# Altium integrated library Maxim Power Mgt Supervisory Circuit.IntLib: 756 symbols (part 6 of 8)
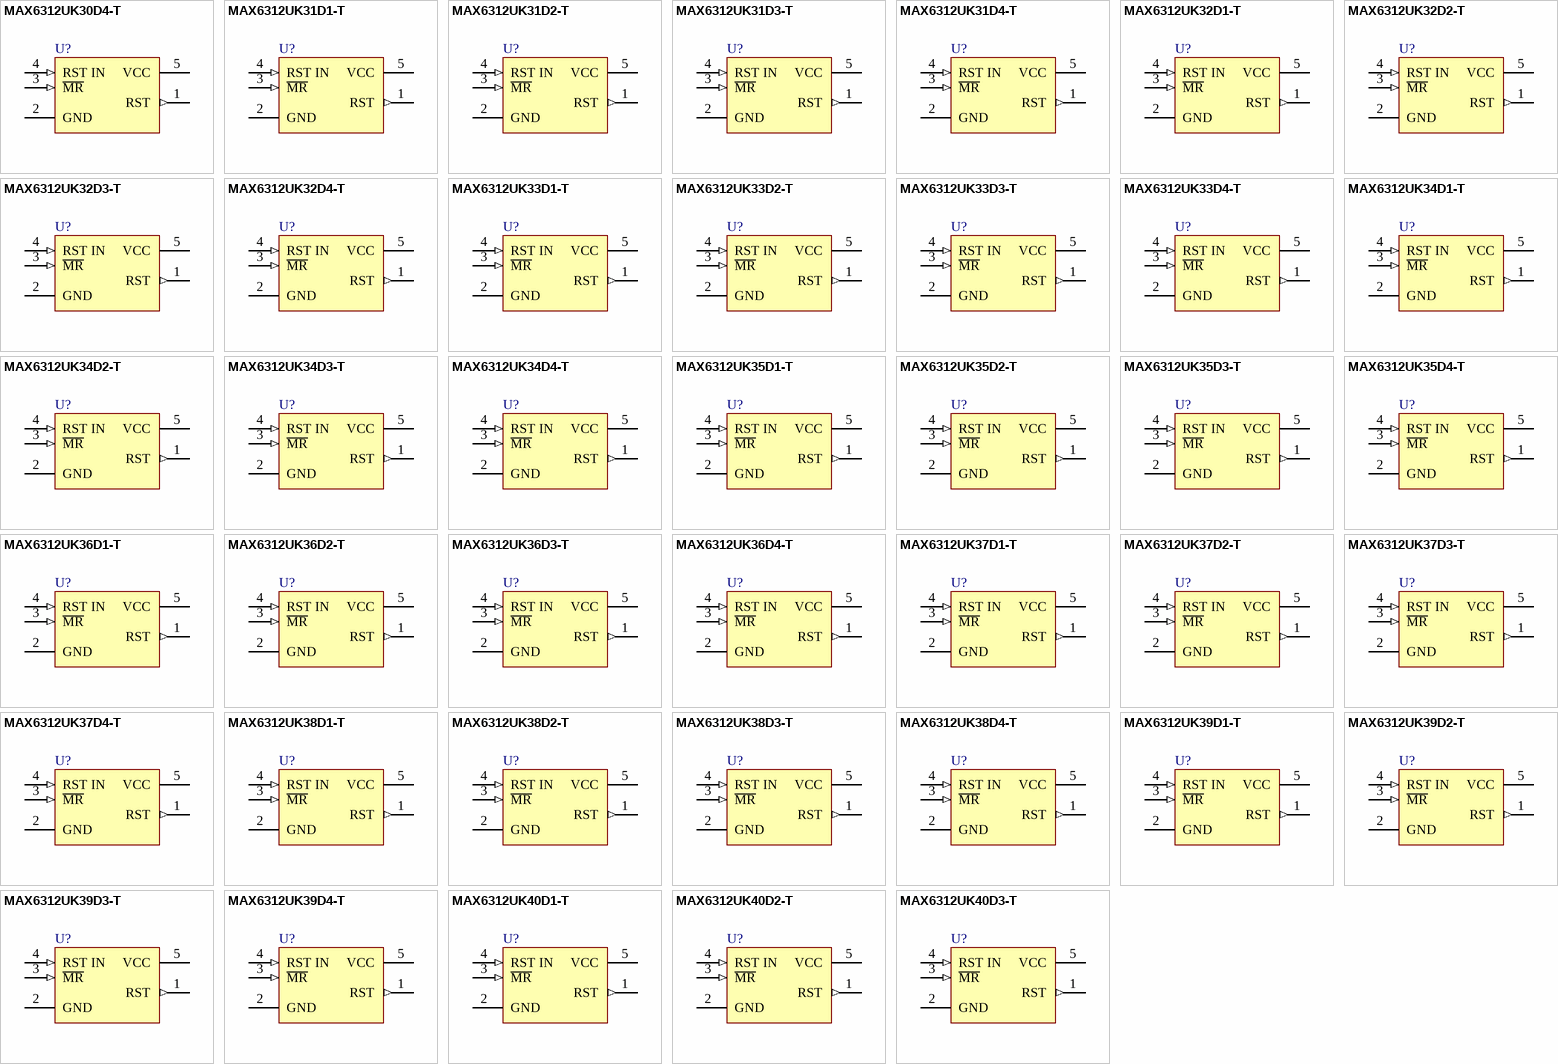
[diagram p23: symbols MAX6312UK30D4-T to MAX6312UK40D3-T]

## MAX6312UK35D3-T
designator U?
5-Pin, Multiple-Input, Programmable Reset IC
footprint SOT23-5_N (SOT23, 5-Leads, Body 2.9x1.6mm, Pitch 0.95mm, Lead Span 2.8mm, IPC Medium Density)
footprint SOT23-5_L (SOT23, 5-Leads, Body 2.9x1.6mm, Pitch 0.95mm, Lead Span 2.8mm, IPC High Density)
footprint SOT23-5_M (SOT23, 5-Leads, Body 2.9x1.6mm, Pitch 0.95mm, Lead Span 2.8mm, IPC Low Density)
pins: 1 RST (out), 2 GND (power), 3 ~{MR} (in), 4 RST IN (in), 5 VCC (power)

## MAX6312UK35D4-T
designator U?
5-Pin, Multiple-Input, Programmable Reset IC
footprint SOT23-5_N (SOT23, 5-Leads, Body 2.9x1.6mm, Pitch 0.95mm, Lead Span 2.8mm, IPC Medium Density)
footprint SOT23-5_L (SOT23, 5-Leads, Body 2.9x1.6mm, Pitch 0.95mm, Lead Span 2.8mm, IPC High Density)
footprint SOT23-5_M (SOT23, 5-Leads, Body 2.9x1.6mm, Pitch 0.95mm, Lead Span 2.8mm, IPC Low Density)
pins: 1 RST (out), 2 GND (power), 3 ~{MR} (in), 4 RST IN (in), 5 VCC (power)

## MAX6312UK36D1-T
designator U?
5-Pin, Multiple-Input, Programmable Reset IC
footprint SOT23-5_N (SOT23, 5-Leads, Body 2.9x1.6mm, Pitch 0.95mm, Lead Span 2.8mm, IPC Medium Density)
footprint SOT23-5_L (SOT23, 5-Leads, Body 2.9x1.6mm, Pitch 0.95mm, Lead Span 2.8mm, IPC High Density)
footprint SOT23-5_M (SOT23, 5-Leads, Body 2.9x1.6mm, Pitch 0.95mm, Lead Span 2.8mm, IPC Low Density)
pins: 1 RST (out), 2 GND (power), 3 ~{MR} (in), 4 RST IN (in), 5 VCC (power)

## MAX6312UK36D2-T
designator U?
5-Pin, Multiple-Input, Programmable Reset IC
footprint SOT23-5_N (SOT23, 5-Leads, Body 2.9x1.6mm, Pitch 0.95mm, Lead Span 2.8mm, IPC Medium Density)
footprint SOT23-5_L (SOT23, 5-Leads, Body 2.9x1.6mm, Pitch 0.95mm, Lead Span 2.8mm, IPC High Density)
footprint SOT23-5_M (SOT23, 5-Leads, Body 2.9x1.6mm, Pitch 0.95mm, Lead Span 2.8mm, IPC Low Density)
pins: 1 RST (out), 2 GND (power), 3 ~{MR} (in), 4 RST IN (in), 5 VCC (power)

## MAX6312UK36D3-T
designator U?
5-Pin, Multiple-Input, Programmable Reset IC
footprint SOT23-5_N (SOT23, 5-Leads, Body 2.9x1.6mm, Pitch 0.95mm, Lead Span 2.8mm, IPC Medium Density)
footprint SOT23-5_L (SOT23, 5-Leads, Body 2.9x1.6mm, Pitch 0.95mm, Lead Span 2.8mm, IPC High Density)
footprint SOT23-5_M (SOT23, 5-Leads, Body 2.9x1.6mm, Pitch 0.95mm, Lead Span 2.8mm, IPC Low Density)
pins: 1 RST (out), 2 GND (power), 3 ~{MR} (in), 4 RST IN (in), 5 VCC (power)

## MAX6312UK36D4-T
designator U?
5-Pin, Multiple-Input, Programmable Reset IC
footprint SOT23-5_N (SOT23, 5-Leads, Body 2.9x1.6mm, Pitch 0.95mm, Lead Span 2.8mm, IPC Medium Density)
footprint SOT23-5_L (SOT23, 5-Leads, Body 2.9x1.6mm, Pitch 0.95mm, Lead Span 2.8mm, IPC High Density)
footprint SOT23-5_M (SOT23, 5-Leads, Body 2.9x1.6mm, Pitch 0.95mm, Lead Span 2.8mm, IPC Low Density)
pins: 1 RST (out), 2 GND (power), 3 ~{MR} (in), 4 RST IN (in), 5 VCC (power)

## MAX6312UK37D1-T
designator U?
5-Pin, Multiple-Input, Programmable Reset IC
footprint SOT23-5_N (SOT23, 5-Leads, Body 2.9x1.6mm, Pitch 0.95mm, Lead Span 2.8mm, IPC Medium Density)
footprint SOT23-5_L (SOT23, 5-Leads, Body 2.9x1.6mm, Pitch 0.95mm, Lead Span 2.8mm, IPC High Density)
footprint SOT23-5_M (SOT23, 5-Leads, Body 2.9x1.6mm, Pitch 0.95mm, Lead Span 2.8mm, IPC Low Density)
pins: 1 RST (out), 2 GND (power), 3 ~{MR} (in), 4 RST IN (in), 5 VCC (power)

## MAX6312UK37D2-T
designator U?
5-Pin, Multiple-Input, Programmable Reset IC
footprint SOT23-5_N (SOT23, 5-Leads, Body 2.9x1.6mm, Pitch 0.95mm, Lead Span 2.8mm, IPC Medium Density)
footprint SOT23-5_L (SOT23, 5-Leads, Body 2.9x1.6mm, Pitch 0.95mm, Lead Span 2.8mm, IPC High Density)
footprint SOT23-5_M (SOT23, 5-Leads, Body 2.9x1.6mm, Pitch 0.95mm, Lead Span 2.8mm, IPC Low Density)
pins: 1 RST (out), 2 GND (power), 3 ~{MR} (in), 4 RST IN (in), 5 VCC (power)

## MAX6312UK37D3-T
designator U?
5-Pin, Multiple-Input, Programmable Reset IC
footprint SOT23-5_N (SOT23, 5-Leads, Body 2.9x1.6mm, Pitch 0.95mm, Lead Span 2.8mm, IPC Medium Density)
footprint SOT23-5_L (SOT23, 5-Leads, Body 2.9x1.6mm, Pitch 0.95mm, Lead Span 2.8mm, IPC High Density)
footprint SOT23-5_M (SOT23, 5-Leads, Body 2.9x1.6mm, Pitch 0.95mm, Lead Span 2.8mm, IPC Low Density)
pins: 1 RST (out), 2 GND (power), 3 ~{MR} (in), 4 RST IN (in), 5 VCC (power)

## MAX6312UK37D4-T
designator U?
5-Pin, Multiple-Input, Programmable Reset IC
footprint SOT23-5_N (SOT23, 5-Leads, Body 2.9x1.6mm, Pitch 0.95mm, Lead Span 2.8mm, IPC Medium Density)
footprint SOT23-5_L (SOT23, 5-Leads, Body 2.9x1.6mm, Pitch 0.95mm, Lead Span 2.8mm, IPC High Density)
footprint SOT23-5_M (SOT23, 5-Leads, Body 2.9x1.6mm, Pitch 0.95mm, Lead Span 2.8mm, IPC Low Density)
pins: 1 RST (out), 2 GND (power), 3 ~{MR} (in), 4 RST IN (in), 5 VCC (power)

## MAX6312UK38D1-T
designator U?
5-Pin, Multiple-Input, Programmable Reset IC
footprint SOT23-5_N (SOT23, 5-Leads, Body 2.9x1.6mm, Pitch 0.95mm, Lead Span 2.8mm, IPC Medium Density)
footprint SOT23-5_L (SOT23, 5-Leads, Body 2.9x1.6mm, Pitch 0.95mm, Lead Span 2.8mm, IPC High Density)
footprint SOT23-5_M (SOT23, 5-Leads, Body 2.9x1.6mm, Pitch 0.95mm, Lead Span 2.8mm, IPC Low Density)
pins: 1 RST (out), 2 GND (power), 3 ~{MR} (in), 4 RST IN (in), 5 VCC (power)

## MAX6312UK38D2-T
designator U?
5-Pin, Multiple-Input, Programmable Reset IC
footprint SOT23-5_N (SOT23, 5-Leads, Body 2.9x1.6mm, Pitch 0.95mm, Lead Span 2.8mm, IPC Medium Density)
footprint SOT23-5_L (SOT23, 5-Leads, Body 2.9x1.6mm, Pitch 0.95mm, Lead Span 2.8mm, IPC High Density)
footprint SOT23-5_M (SOT23, 5-Leads, Body 2.9x1.6mm, Pitch 0.95mm, Lead Span 2.8mm, IPC Low Density)
pins: 1 RST (out), 2 GND (power), 3 ~{MR} (in), 4 RST IN (in), 5 VCC (power)

## MAX6312UK38D3-T
designator U?
5-Pin, Multiple-Input, Programmable Reset IC
footprint SOT23-5_N (SOT23, 5-Leads, Body 2.9x1.6mm, Pitch 0.95mm, Lead Span 2.8mm, IPC Medium Density)
footprint SOT23-5_L (SOT23, 5-Leads, Body 2.9x1.6mm, Pitch 0.95mm, Lead Span 2.8mm, IPC High Density)
footprint SOT23-5_M (SOT23, 5-Leads, Body 2.9x1.6mm, Pitch 0.95mm, Lead Span 2.8mm, IPC Low Density)
pins: 1 RST (out), 2 GND (power), 3 ~{MR} (in), 4 RST IN (in), 5 VCC (power)

## MAX6312UK38D4-T
designator U?
5-Pin, Multiple-Input, Programmable Reset IC
footprint SOT23-5_N (SOT23, 5-Leads, Body 2.9x1.6mm, Pitch 0.95mm, Lead Span 2.8mm, IPC Medium Density)
footprint SOT23-5_L (SOT23, 5-Leads, Body 2.9x1.6mm, Pitch 0.95mm, Lead Span 2.8mm, IPC High Density)
footprint SOT23-5_M (SOT23, 5-Leads, Body 2.9x1.6mm, Pitch 0.95mm, Lead Span 2.8mm, IPC Low Density)
pins: 1 RST (out), 2 GND (power), 3 ~{MR} (in), 4 RST IN (in), 5 VCC (power)

## MAX6312UK39D1-T
designator U?
5-Pin, Multiple-Input, Programmable Reset IC
footprint SOT23-5_N (SOT23, 5-Leads, Body 2.9x1.6mm, Pitch 0.95mm, Lead Span 2.8mm, IPC Medium Density)
footprint SOT23-5_L (SOT23, 5-Leads, Body 2.9x1.6mm, Pitch 0.95mm, Lead Span 2.8mm, IPC High Density)
footprint SOT23-5_M (SOT23, 5-Leads, Body 2.9x1.6mm, Pitch 0.95mm, Lead Span 2.8mm, IPC Low Density)
pins: 1 RST (out), 2 GND (power), 3 ~{MR} (in), 4 RST IN (in), 5 VCC (power)

## MAX6312UK39D2-T
designator U?
5-Pin, Multiple-Input, Programmable Reset IC
footprint SOT23-5_N (SOT23, 5-Leads, Body 2.9x1.6mm, Pitch 0.95mm, Lead Span 2.8mm, IPC Medium Density)
footprint SOT23-5_L (SOT23, 5-Leads, Body 2.9x1.6mm, Pitch 0.95mm, Lead Span 2.8mm, IPC High Density)
footprint SOT23-5_M (SOT23, 5-Leads, Body 2.9x1.6mm, Pitch 0.95mm, Lead Span 2.8mm, IPC Low Density)
pins: 1 RST (out), 2 GND (power), 3 ~{MR} (in), 4 RST IN (in), 5 VCC (power)

## MAX6312UK39D3-T
designator U?
5-Pin, Multiple-Input, Programmable Reset IC
footprint SOT23-5_N (SOT23, 5-Leads, Body 2.9x1.6mm, Pitch 0.95mm, Lead Span 2.8mm, IPC Medium Density)
footprint SOT23-5_L (SOT23, 5-Leads, Body 2.9x1.6mm, Pitch 0.95mm, Lead Span 2.8mm, IPC High Density)
footprint SOT23-5_M (SOT23, 5-Leads, Body 2.9x1.6mm, Pitch 0.95mm, Lead Span 2.8mm, IPC Low Density)
pins: 1 RST (out), 2 GND (power), 3 ~{MR} (in), 4 RST IN (in), 5 VCC (power)

## MAX6312UK39D4-T
designator U?
5-Pin, Multiple-Input, Programmable Reset IC
footprint SOT23-5_N (SOT23, 5-Leads, Body 2.9x1.6mm, Pitch 0.95mm, Lead Span 2.8mm, IPC Medium Density)
footprint SOT23-5_L (SOT23, 5-Leads, Body 2.9x1.6mm, Pitch 0.95mm, Lead Span 2.8mm, IPC High Density)
footprint SOT23-5_M (SOT23, 5-Leads, Body 2.9x1.6mm, Pitch 0.95mm, Lead Span 2.8mm, IPC Low Density)
pins: 1 RST (out), 2 GND (power), 3 ~{MR} (in), 4 RST IN (in), 5 VCC (power)

## MAX6312UK40D1-T
designator U?
5-Pin, Multiple-Input, Programmable Reset IC
footprint SOT23-5_N (SOT23, 5-Leads, Body 2.9x1.6mm, Pitch 0.95mm, Lead Span 2.8mm, IPC Medium Density)
footprint SOT23-5_L (SOT23, 5-Leads, Body 2.9x1.6mm, Pitch 0.95mm, Lead Span 2.8mm, IPC High Density)
footprint SOT23-5_M (SOT23, 5-Leads, Body 2.9x1.6mm, Pitch 0.95mm, Lead Span 2.8mm, IPC Low Density)
pins: 1 RST (out), 2 GND (power), 3 ~{MR} (in), 4 RST IN (in), 5 VCC (power)

## MAX6312UK40D2-T
designator U?
5-Pin, Multiple-Input, Programmable Reset IC
footprint SOT23-5_N (SOT23, 5-Leads, Body 2.9x1.6mm, Pitch 0.95mm, Lead Span 2.8mm, IPC Medium Density)
footprint SOT23-5_L (SOT23, 5-Leads, Body 2.9x1.6mm, Pitch 0.95mm, Lead Span 2.8mm, IPC High Density)
footprint SOT23-5_M (SOT23, 5-Leads, Body 2.9x1.6mm, Pitch 0.95mm, Lead Span 2.8mm, IPC Low Density)
pins: 1 RST (out), 2 GND (power), 3 ~{MR} (in), 4 RST IN (in), 5 VCC (power)

## MAX6312UK40D3-T
designator U?
5-Pin, Multiple-Input, Programmable Reset IC
footprint SOT23-5_N (SOT23, 5-Leads, Body 2.9x1.6mm, Pitch 0.95mm, Lead Span 2.8mm, IPC Medium Density)
footprint SOT23-5_L (SOT23, 5-Leads, Body 2.9x1.6mm, Pitch 0.95mm, Lead Span 2.8mm, IPC High Density)
footprint SOT23-5_M (SOT23, 5-Leads, Body 2.9x1.6mm, Pitch 0.95mm, Lead Span 2.8mm, IPC Low Density)
pins: 1 RST (out), 2 GND (power), 3 ~{MR} (in), 4 RST IN (in), 5 VCC (power)

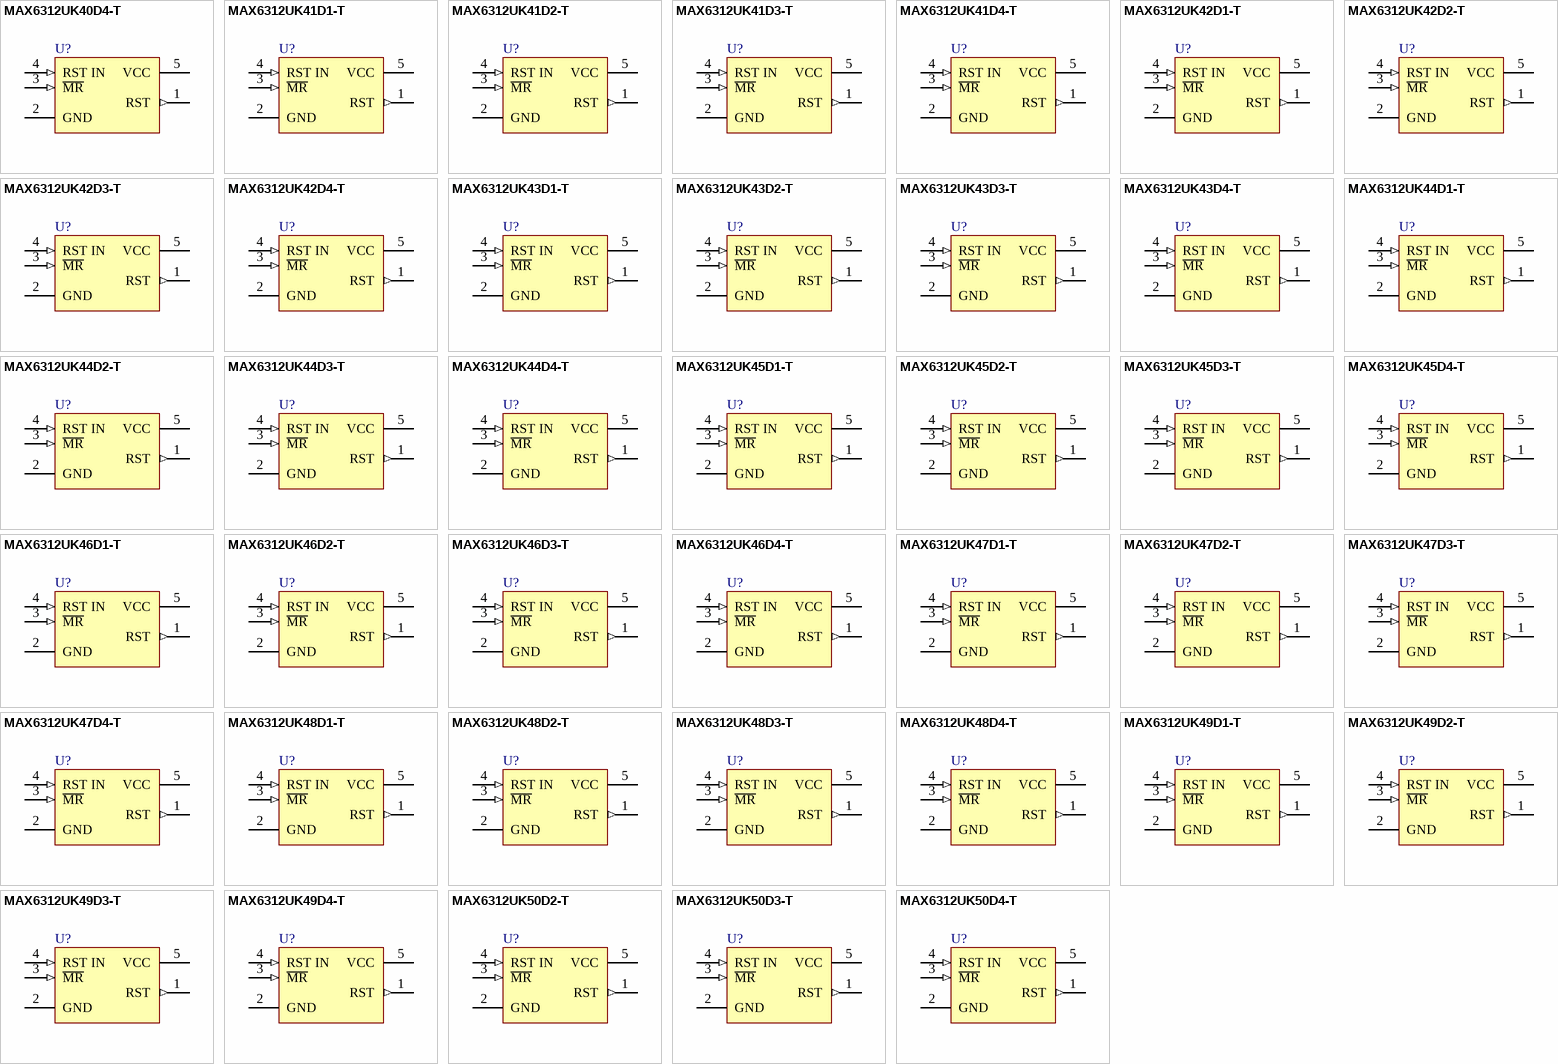
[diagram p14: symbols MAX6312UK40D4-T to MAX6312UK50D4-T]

## MAX6312UK40D4-T
designator U?
5-Pin, Multiple-Input, Programmable Reset IC
footprint SOT23-5_N (SOT23, 5-Leads, Body 2.9x1.6mm, Pitch 0.95mm, Lead Span 2.8mm, IPC Medium Density)
footprint SOT23-5_L (SOT23, 5-Leads, Body 2.9x1.6mm, Pitch 0.95mm, Lead Span 2.8mm, IPC High Density)
footprint SOT23-5_M (SOT23, 5-Leads, Body 2.9x1.6mm, Pitch 0.95mm, Lead Span 2.8mm, IPC Low Density)
pins: 1 RST (out), 2 GND (power), 3 ~{MR} (in), 4 RST IN (in), 5 VCC (power)

## MAX6312UK41D1-T
designator U?
5-Pin, Multiple-Input, Programmable Reset IC
footprint SOT23-5_N (SOT23, 5-Leads, Body 2.9x1.6mm, Pitch 0.95mm, Lead Span 2.8mm, IPC Medium Density)
footprint SOT23-5_L (SOT23, 5-Leads, Body 2.9x1.6mm, Pitch 0.95mm, Lead Span 2.8mm, IPC High Density)
footprint SOT23-5_M (SOT23, 5-Leads, Body 2.9x1.6mm, Pitch 0.95mm, Lead Span 2.8mm, IPC Low Density)
pins: 1 RST (out), 2 GND (power), 3 ~{MR} (in), 4 RST IN (in), 5 VCC (power)

## MAX6312UK41D2-T
designator U?
5-Pin, Multiple-Input, Programmable Reset IC
footprint SOT23-5_N (SOT23, 5-Leads, Body 2.9x1.6mm, Pitch 0.95mm, Lead Span 2.8mm, IPC Medium Density)
footprint SOT23-5_L (SOT23, 5-Leads, Body 2.9x1.6mm, Pitch 0.95mm, Lead Span 2.8mm, IPC High Density)
footprint SOT23-5_M (SOT23, 5-Leads, Body 2.9x1.6mm, Pitch 0.95mm, Lead Span 2.8mm, IPC Low Density)
pins: 1 RST (out), 2 GND (power), 3 ~{MR} (in), 4 RST IN (in), 5 VCC (power)

## MAX6312UK41D3-T
designator U?
5-Pin, Multiple-Input, Programmable Reset IC
footprint SOT23-5_N (SOT23, 5-Leads, Body 2.9x1.6mm, Pitch 0.95mm, Lead Span 2.8mm, IPC Medium Density)
footprint SOT23-5_L (SOT23, 5-Leads, Body 2.9x1.6mm, Pitch 0.95mm, Lead Span 2.8mm, IPC High Density)
footprint SOT23-5_M (SOT23, 5-Leads, Body 2.9x1.6mm, Pitch 0.95mm, Lead Span 2.8mm, IPC Low Density)
pins: 1 RST (out), 2 GND (power), 3 ~{MR} (in), 4 RST IN (in), 5 VCC (power)

## MAX6312UK41D4-T
designator U?
5-Pin, Multiple-Input, Programmable Reset IC
footprint SOT23-5_N (SOT23, 5-Leads, Body 2.9x1.6mm, Pitch 0.95mm, Lead Span 2.8mm, IPC Medium Density)
footprint SOT23-5_L (SOT23, 5-Leads, Body 2.9x1.6mm, Pitch 0.95mm, Lead Span 2.8mm, IPC High Density)
footprint SOT23-5_M (SOT23, 5-Leads, Body 2.9x1.6mm, Pitch 0.95mm, Lead Span 2.8mm, IPC Low Density)
pins: 1 RST (out), 2 GND (power), 3 ~{MR} (in), 4 RST IN (in), 5 VCC (power)

## MAX6312UK42D1-T
designator U?
5-Pin, Multiple-Input, Programmable Reset IC
footprint SOT23-5_N (SOT23, 5-Leads, Body 2.9x1.6mm, Pitch 0.95mm, Lead Span 2.8mm, IPC Medium Density)
footprint SOT23-5_L (SOT23, 5-Leads, Body 2.9x1.6mm, Pitch 0.95mm, Lead Span 2.8mm, IPC High Density)
footprint SOT23-5_M (SOT23, 5-Leads, Body 2.9x1.6mm, Pitch 0.95mm, Lead Span 2.8mm, IPC Low Density)
pins: 1 RST (out), 2 GND (power), 3 ~{MR} (in), 4 RST IN (in), 5 VCC (power)

## MAX6312UK42D2-T
designator U?
5-Pin, Multiple-Input, Programmable Reset IC
footprint SOT23-5_N (SOT23, 5-Leads, Body 2.9x1.6mm, Pitch 0.95mm, Lead Span 2.8mm, IPC Medium Density)
footprint SOT23-5_L (SOT23, 5-Leads, Body 2.9x1.6mm, Pitch 0.95mm, Lead Span 2.8mm, IPC High Density)
footprint SOT23-5_M (SOT23, 5-Leads, Body 2.9x1.6mm, Pitch 0.95mm, Lead Span 2.8mm, IPC Low Density)
pins: 1 RST (out), 2 GND (power), 3 ~{MR} (in), 4 RST IN (in), 5 VCC (power)

## MAX6312UK42D3-T
designator U?
5-Pin, Multiple-Input, Programmable Reset IC
footprint SOT23-5_N (SOT23, 5-Leads, Body 2.9x1.6mm, Pitch 0.95mm, Lead Span 2.8mm, IPC Medium Density)
footprint SOT23-5_L (SOT23, 5-Leads, Body 2.9x1.6mm, Pitch 0.95mm, Lead Span 2.8mm, IPC High Density)
footprint SOT23-5_M (SOT23, 5-Leads, Body 2.9x1.6mm, Pitch 0.95mm, Lead Span 2.8mm, IPC Low Density)
pins: 1 RST (out), 2 GND (power), 3 ~{MR} (in), 4 RST IN (in), 5 VCC (power)

## MAX6312UK42D4-T
designator U?
5-Pin, Multiple-Input, Programmable Reset IC
footprint SOT23-5_N (SOT23, 5-Leads, Body 2.9x1.6mm, Pitch 0.95mm, Lead Span 2.8mm, IPC Medium Density)
footprint SOT23-5_L (SOT23, 5-Leads, Body 2.9x1.6mm, Pitch 0.95mm, Lead Span 2.8mm, IPC High Density)
footprint SOT23-5_M (SOT23, 5-Leads, Body 2.9x1.6mm, Pitch 0.95mm, Lead Span 2.8mm, IPC Low Density)
pins: 1 RST (out), 2 GND (power), 3 ~{MR} (in), 4 RST IN (in), 5 VCC (power)

## MAX6312UK43D1-T
designator U?
5-Pin, Multiple-Input, Programmable Reset IC
footprint SOT23-5_N (SOT23, 5-Leads, Body 2.9x1.6mm, Pitch 0.95mm, Lead Span 2.8mm, IPC Medium Density)
footprint SOT23-5_L (SOT23, 5-Leads, Body 2.9x1.6mm, Pitch 0.95mm, Lead Span 2.8mm, IPC High Density)
footprint SOT23-5_M (SOT23, 5-Leads, Body 2.9x1.6mm, Pitch 0.95mm, Lead Span 2.8mm, IPC Low Density)
pins: 1 RST (out), 2 GND (power), 3 ~{MR} (in), 4 RST IN (in), 5 VCC (power)

## MAX6312UK43D2-T
designator U?
5-Pin, Multiple-Input, Programmable Reset IC
footprint SOT23-5_N (SOT23, 5-Leads, Body 2.9x1.6mm, Pitch 0.95mm, Lead Span 2.8mm, IPC Medium Density)
footprint SOT23-5_L (SOT23, 5-Leads, Body 2.9x1.6mm, Pitch 0.95mm, Lead Span 2.8mm, IPC High Density)
footprint SOT23-5_M (SOT23, 5-Leads, Body 2.9x1.6mm, Pitch 0.95mm, Lead Span 2.8mm, IPC Low Density)
pins: 1 RST (out), 2 GND (power), 3 ~{MR} (in), 4 RST IN (in), 5 VCC (power)

## MAX6312UK43D3-T
designator U?
5-Pin, Multiple-Input, Programmable Reset IC
footprint SOT23-5_N (SOT23, 5-Leads, Body 2.9x1.6mm, Pitch 0.95mm, Lead Span 2.8mm, IPC Medium Density)
footprint SOT23-5_L (SOT23, 5-Leads, Body 2.9x1.6mm, Pitch 0.95mm, Lead Span 2.8mm, IPC High Density)
footprint SOT23-5_M (SOT23, 5-Leads, Body 2.9x1.6mm, Pitch 0.95mm, Lead Span 2.8mm, IPC Low Density)
pins: 1 RST (out), 2 GND (power), 3 ~{MR} (in), 4 RST IN (in), 5 VCC (power)

## MAX6312UK43D4-T
designator U?
5-Pin, Multiple-Input, Programmable Reset IC
footprint SOT23-5_N (SOT23, 5-Leads, Body 2.9x1.6mm, Pitch 0.95mm, Lead Span 2.8mm, IPC Medium Density)
footprint SOT23-5_L (SOT23, 5-Leads, Body 2.9x1.6mm, Pitch 0.95mm, Lead Span 2.8mm, IPC High Density)
footprint SOT23-5_M (SOT23, 5-Leads, Body 2.9x1.6mm, Pitch 0.95mm, Lead Span 2.8mm, IPC Low Density)
pins: 1 RST (out), 2 GND (power), 3 ~{MR} (in), 4 RST IN (in), 5 VCC (power)

## MAX6312UK44D1-T
designator U?
5-Pin, Multiple-Input, Programmable Reset IC
footprint SOT23-5_N (SOT23, 5-Leads, Body 2.9x1.6mm, Pitch 0.95mm, Lead Span 2.8mm, IPC Medium Density)
footprint SOT23-5_L (SOT23, 5-Leads, Body 2.9x1.6mm, Pitch 0.95mm, Lead Span 2.8mm, IPC High Density)
footprint SOT23-5_M (SOT23, 5-Leads, Body 2.9x1.6mm, Pitch 0.95mm, Lead Span 2.8mm, IPC Low Density)
pins: 1 RST (out), 2 GND (power), 3 ~{MR} (in), 4 RST IN (in), 5 VCC (power)

## MAX6312UK44D2-T
designator U?
5-Pin, Multiple-Input, Programmable Reset IC
footprint SOT23-5_N (SOT23, 5-Leads, Body 2.9x1.6mm, Pitch 0.95mm, Lead Span 2.8mm, IPC Medium Density)
footprint SOT23-5_L (SOT23, 5-Leads, Body 2.9x1.6mm, Pitch 0.95mm, Lead Span 2.8mm, IPC High Density)
footprint SOT23-5_M (SOT23, 5-Leads, Body 2.9x1.6mm, Pitch 0.95mm, Lead Span 2.8mm, IPC Low Density)
pins: 1 RST (out), 2 GND (power), 3 ~{MR} (in), 4 RST IN (in), 5 VCC (power)

## MAX6312UK44D3-T
designator U?
5-Pin, Multiple-Input, Programmable Reset IC
footprint SOT23-5_N (SOT23, 5-Leads, Body 2.9x1.6mm, Pitch 0.95mm, Lead Span 2.8mm, IPC Medium Density)
footprint SOT23-5_L (SOT23, 5-Leads, Body 2.9x1.6mm, Pitch 0.95mm, Lead Span 2.8mm, IPC High Density)
footprint SOT23-5_M (SOT23, 5-Leads, Body 2.9x1.6mm, Pitch 0.95mm, Lead Span 2.8mm, IPC Low Density)
pins: 1 RST (out), 2 GND (power), 3 ~{MR} (in), 4 RST IN (in), 5 VCC (power)

## MAX6312UK44D4-T
designator U?
5-Pin, Multiple-Input, Programmable Reset IC
footprint SOT23-5_N (SOT23, 5-Leads, Body 2.9x1.6mm, Pitch 0.95mm, Lead Span 2.8mm, IPC Medium Density)
footprint SOT23-5_L (SOT23, 5-Leads, Body 2.9x1.6mm, Pitch 0.95mm, Lead Span 2.8mm, IPC High Density)
footprint SOT23-5_M (SOT23, 5-Leads, Body 2.9x1.6mm, Pitch 0.95mm, Lead Span 2.8mm, IPC Low Density)
pins: 1 RST (out), 2 GND (power), 3 ~{MR} (in), 4 RST IN (in), 5 VCC (power)

## MAX6312UK45D1-T
designator U?
5-Pin, Multiple-Input, Programmable Reset IC
footprint SOT23-5_N (SOT23, 5-Leads, Body 2.9x1.6mm, Pitch 0.95mm, Lead Span 2.8mm, IPC Medium Density)
footprint SOT23-5_L (SOT23, 5-Leads, Body 2.9x1.6mm, Pitch 0.95mm, Lead Span 2.8mm, IPC High Density)
footprint SOT23-5_M (SOT23, 5-Leads, Body 2.9x1.6mm, Pitch 0.95mm, Lead Span 2.8mm, IPC Low Density)
pins: 1 RST (out), 2 GND (power), 3 ~{MR} (in), 4 RST IN (in), 5 VCC (power)

## MAX6312UK45D2-T
designator U?
5-Pin, Multiple-Input, Programmable Reset IC
footprint SOT23-5_N (SOT23, 5-Leads, Body 2.9x1.6mm, Pitch 0.95mm, Lead Span 2.8mm, IPC Medium Density)
footprint SOT23-5_L (SOT23, 5-Leads, Body 2.9x1.6mm, Pitch 0.95mm, Lead Span 2.8mm, IPC High Density)
footprint SOT23-5_M (SOT23, 5-Leads, Body 2.9x1.6mm, Pitch 0.95mm, Lead Span 2.8mm, IPC Low Density)
pins: 1 RST (out), 2 GND (power), 3 ~{MR} (in), 4 RST IN (in), 5 VCC (power)

## MAX6312UK45D3-T
designator U?
5-Pin, Multiple-Input, Programmable Reset IC
footprint SOT23-5_N (SOT23, 5-Leads, Body 2.9x1.6mm, Pitch 0.95mm, Lead Span 2.8mm, IPC Medium Density)
footprint SOT23-5_L (SOT23, 5-Leads, Body 2.9x1.6mm, Pitch 0.95mm, Lead Span 2.8mm, IPC High Density)
footprint SOT23-5_M (SOT23, 5-Leads, Body 2.9x1.6mm, Pitch 0.95mm, Lead Span 2.8mm, IPC Low Density)
pins: 1 RST (out), 2 GND (power), 3 ~{MR} (in), 4 RST IN (in), 5 VCC (power)

## MAX6312UK45D4-T
designator U?
5-Pin, Multiple-Input, Programmable Reset IC
footprint SOT23-5_N (SOT23, 5-Leads, Body 2.9x1.6mm, Pitch 0.95mm, Lead Span 2.8mm, IPC Medium Density)
footprint SOT23-5_L (SOT23, 5-Leads, Body 2.9x1.6mm, Pitch 0.95mm, Lead Span 2.8mm, IPC High Density)
footprint SOT23-5_M (SOT23, 5-Leads, Body 2.9x1.6mm, Pitch 0.95mm, Lead Span 2.8mm, IPC Low Density)
pins: 1 RST (out), 2 GND (power), 3 ~{MR} (in), 4 RST IN (in), 5 VCC (power)

## MAX6312UK46D1-T
designator U?
5-Pin, Multiple-Input, Programmable Reset IC
footprint SOT23-5_N (SOT23, 5-Leads, Body 2.9x1.6mm, Pitch 0.95mm, Lead Span 2.8mm, IPC Medium Density)
footprint SOT23-5_L (SOT23, 5-Leads, Body 2.9x1.6mm, Pitch 0.95mm, Lead Span 2.8mm, IPC High Density)
footprint SOT23-5_M (SOT23, 5-Leads, Body 2.9x1.6mm, Pitch 0.95mm, Lead Span 2.8mm, IPC Low Density)
pins: 1 RST (out), 2 GND (power), 3 ~{MR} (in), 4 RST IN (in), 5 VCC (power)

## MAX6312UK46D2-T
designator U?
5-Pin, Multiple-Input, Programmable Reset IC
footprint SOT23-5_N (SOT23, 5-Leads, Body 2.9x1.6mm, Pitch 0.95mm, Lead Span 2.8mm, IPC Medium Density)
footprint SOT23-5_L (SOT23, 5-Leads, Body 2.9x1.6mm, Pitch 0.95mm, Lead Span 2.8mm, IPC High Density)
footprint SOT23-5_M (SOT23, 5-Leads, Body 2.9x1.6mm, Pitch 0.95mm, Lead Span 2.8mm, IPC Low Density)
pins: 1 RST (out), 2 GND (power), 3 ~{MR} (in), 4 RST IN (in), 5 VCC (power)

## MAX6312UK46D3-T
designator U?
5-Pin, Multiple-Input, Programmable Reset IC
footprint SOT23-5_N (SOT23, 5-Leads, Body 2.9x1.6mm, Pitch 0.95mm, Lead Span 2.8mm, IPC Medium Density)
footprint SOT23-5_L (SOT23, 5-Leads, Body 2.9x1.6mm, Pitch 0.95mm, Lead Span 2.8mm, IPC High Density)
footprint SOT23-5_M (SOT23, 5-Leads, Body 2.9x1.6mm, Pitch 0.95mm, Lead Span 2.8mm, IPC Low Density)
pins: 1 RST (out), 2 GND (power), 3 ~{MR} (in), 4 RST IN (in), 5 VCC (power)

## MAX6312UK46D4-T
designator U?
5-Pin, Multiple-Input, Programmable Reset IC
footprint SOT23-5_N (SOT23, 5-Leads, Body 2.9x1.6mm, Pitch 0.95mm, Lead Span 2.8mm, IPC Medium Density)
footprint SOT23-5_L (SOT23, 5-Leads, Body 2.9x1.6mm, Pitch 0.95mm, Lead Span 2.8mm, IPC High Density)
footprint SOT23-5_M (SOT23, 5-Leads, Body 2.9x1.6mm, Pitch 0.95mm, Lead Span 2.8mm, IPC Low Density)
pins: 1 RST (out), 2 GND (power), 3 ~{MR} (in), 4 RST IN (in), 5 VCC (power)

## MAX6312UK47D1-T
designator U?
5-Pin, Multiple-Input, Programmable Reset IC
footprint SOT23-5_N (SOT23, 5-Leads, Body 2.9x1.6mm, Pitch 0.95mm, Lead Span 2.8mm, IPC Medium Density)
footprint SOT23-5_L (SOT23, 5-Leads, Body 2.9x1.6mm, Pitch 0.95mm, Lead Span 2.8mm, IPC High Density)
footprint SOT23-5_M (SOT23, 5-Leads, Body 2.9x1.6mm, Pitch 0.95mm, Lead Span 2.8mm, IPC Low Density)
pins: 1 RST (out), 2 GND (power), 3 ~{MR} (in), 4 RST IN (in), 5 VCC (power)

## MAX6312UK47D2-T
designator U?
5-Pin, Multiple-Input, Programmable Reset IC
footprint SOT23-5_N (SOT23, 5-Leads, Body 2.9x1.6mm, Pitch 0.95mm, Lead Span 2.8mm, IPC Medium Density)
footprint SOT23-5_L (SOT23, 5-Leads, Body 2.9x1.6mm, Pitch 0.95mm, Lead Span 2.8mm, IPC High Density)
footprint SOT23-5_M (SOT23, 5-Leads, Body 2.9x1.6mm, Pitch 0.95mm, Lead Span 2.8mm, IPC Low Density)
pins: 1 RST (out), 2 GND (power), 3 ~{MR} (in), 4 RST IN (in), 5 VCC (power)

## MAX6312UK47D3-T
designator U?
5-Pin, Multiple-Input, Programmable Reset IC
footprint SOT23-5_N (SOT23, 5-Leads, Body 2.9x1.6mm, Pitch 0.95mm, Lead Span 2.8mm, IPC Medium Density)
footprint SOT23-5_L (SOT23, 5-Leads, Body 2.9x1.6mm, Pitch 0.95mm, Lead Span 2.8mm, IPC High Density)
footprint SOT23-5_M (SOT23, 5-Leads, Body 2.9x1.6mm, Pitch 0.95mm, Lead Span 2.8mm, IPC Low Density)
pins: 1 RST (out), 2 GND (power), 3 ~{MR} (in), 4 RST IN (in), 5 VCC (power)

## MAX6312UK47D4-T
designator U?
5-Pin, Multiple-Input, Programmable Reset IC
footprint SOT23-5_N (SOT23, 5-Leads, Body 2.9x1.6mm, Pitch 0.95mm, Lead Span 2.8mm, IPC Medium Density)
footprint SOT23-5_L (SOT23, 5-Leads, Body 2.9x1.6mm, Pitch 0.95mm, Lead Span 2.8mm, IPC High Density)
footprint SOT23-5_M (SOT23, 5-Leads, Body 2.9x1.6mm, Pitch 0.95mm, Lead Span 2.8mm, IPC Low Density)
pins: 1 RST (out), 2 GND (power), 3 ~{MR} (in), 4 RST IN (in), 5 VCC (power)

## MAX6312UK48D1-T
designator U?
5-Pin, Multiple-Input, Programmable Reset IC
footprint SOT23-5_N (SOT23, 5-Leads, Body 2.9x1.6mm, Pitch 0.95mm, Lead Span 2.8mm, IPC Medium Density)
footprint SOT23-5_L (SOT23, 5-Leads, Body 2.9x1.6mm, Pitch 0.95mm, Lead Span 2.8mm, IPC High Density)
footprint SOT23-5_M (SOT23, 5-Leads, Body 2.9x1.6mm, Pitch 0.95mm, Lead Span 2.8mm, IPC Low Density)
pins: 1 RST (out), 2 GND (power), 3 ~{MR} (in), 4 RST IN (in), 5 VCC (power)

## MAX6312UK48D2-T
designator U?
5-Pin, Multiple-Input, Programmable Reset IC
footprint SOT23-5_N (SOT23, 5-Leads, Body 2.9x1.6mm, Pitch 0.95mm, Lead Span 2.8mm, IPC Medium Density)
footprint SOT23-5_L (SOT23, 5-Leads, Body 2.9x1.6mm, Pitch 0.95mm, Lead Span 2.8mm, IPC High Density)
footprint SOT23-5_M (SOT23, 5-Leads, Body 2.9x1.6mm, Pitch 0.95mm, Lead Span 2.8mm, IPC Low Density)
pins: 1 RST (out), 2 GND (power), 3 ~{MR} (in), 4 RST IN (in), 5 VCC (power)

## MAX6312UK48D3-T
designator U?
5-Pin, Multiple-Input, Programmable Reset IC
footprint SOT23-5_N (SOT23, 5-Leads, Body 2.9x1.6mm, Pitch 0.95mm, Lead Span 2.8mm, IPC Medium Density)
footprint SOT23-5_L (SOT23, 5-Leads, Body 2.9x1.6mm, Pitch 0.95mm, Lead Span 2.8mm, IPC High Density)
footprint SOT23-5_M (SOT23, 5-Leads, Body 2.9x1.6mm, Pitch 0.95mm, Lead Span 2.8mm, IPC Low Density)
pins: 1 RST (out), 2 GND (power), 3 ~{MR} (in), 4 RST IN (in), 5 VCC (power)

## MAX6312UK48D4-T
designator U?
5-Pin, Multiple-Input, Programmable Reset IC
footprint SOT23-5_N (SOT23, 5-Leads, Body 2.9x1.6mm, Pitch 0.95mm, Lead Span 2.8mm, IPC Medium Density)
footprint SOT23-5_L (SOT23, 5-Leads, Body 2.9x1.6mm, Pitch 0.95mm, Lead Span 2.8mm, IPC High Density)
footprint SOT23-5_M (SOT23, 5-Leads, Body 2.9x1.6mm, Pitch 0.95mm, Lead Span 2.8mm, IPC Low Density)
pins: 1 RST (out), 2 GND (power), 3 ~{MR} (in), 4 RST IN (in), 5 VCC (power)

## MAX6312UK49D1-T
designator U?
5-Pin, Multiple-Input, Programmable Reset IC
footprint SOT23-5_N (SOT23, 5-Leads, Body 2.9x1.6mm, Pitch 0.95mm, Lead Span 2.8mm, IPC Medium Density)
footprint SOT23-5_L (SOT23, 5-Leads, Body 2.9x1.6mm, Pitch 0.95mm, Lead Span 2.8mm, IPC High Density)
footprint SOT23-5_M (SOT23, 5-Leads, Body 2.9x1.6mm, Pitch 0.95mm, Lead Span 2.8mm, IPC Low Density)
pins: 1 RST (out), 2 GND (power), 3 ~{MR} (in), 4 RST IN (in), 5 VCC (power)

## MAX6312UK49D2-T
designator U?
5-Pin, Multiple-Input, Programmable Reset IC
footprint SOT23-5_N (SOT23, 5-Leads, Body 2.9x1.6mm, Pitch 0.95mm, Lead Span 2.8mm, IPC Medium Density)
footprint SOT23-5_L (SOT23, 5-Leads, Body 2.9x1.6mm, Pitch 0.95mm, Lead Span 2.8mm, IPC High Density)
footprint SOT23-5_M (SOT23, 5-Leads, Body 2.9x1.6mm, Pitch 0.95mm, Lead Span 2.8mm, IPC Low Density)
pins: 1 RST (out), 2 GND (power), 3 ~{MR} (in), 4 RST IN (in), 5 VCC (power)

## MAX6312UK49D3-T
designator U?
5-Pin, Multiple-Input, Programmable Reset IC
footprint SOT23-5_N (SOT23, 5-Leads, Body 2.9x1.6mm, Pitch 0.95mm, Lead Span 2.8mm, IPC Medium Density)
footprint SOT23-5_L (SOT23, 5-Leads, Body 2.9x1.6mm, Pitch 0.95mm, Lead Span 2.8mm, IPC High Density)
footprint SOT23-5_M (SOT23, 5-Leads, Body 2.9x1.6mm, Pitch 0.95mm, Lead Span 2.8mm, IPC Low Density)
pins: 1 RST (out), 2 GND (power), 3 ~{MR} (in), 4 RST IN (in), 5 VCC (power)

## MAX6312UK49D4-T
designator U?
5-Pin, Multiple-Input, Programmable Reset IC
footprint SOT23-5_N (SOT23, 5-Leads, Body 2.9x1.6mm, Pitch 0.95mm, Lead Span 2.8mm, IPC Medium Density)
footprint SOT23-5_L (SOT23, 5-Leads, Body 2.9x1.6mm, Pitch 0.95mm, Lead Span 2.8mm, IPC High Density)
footprint SOT23-5_M (SOT23, 5-Leads, Body 2.9x1.6mm, Pitch 0.95mm, Lead Span 2.8mm, IPC Low Density)
pins: 1 RST (out), 2 GND (power), 3 ~{MR} (in), 4 RST IN (in), 5 VCC (power)

## MAX6312UK50D2-T
designator U?
5-Pin, Multiple-Input, Programmable Reset IC
footprint SOT23-5_N (SOT23, 5-Leads, Body 2.9x1.6mm, Pitch 0.95mm, Lead Span 2.8mm, IPC Medium Density)
footprint SOT23-5_L (SOT23, 5-Leads, Body 2.9x1.6mm, Pitch 0.95mm, Lead Span 2.8mm, IPC High Density)
footprint SOT23-5_M (SOT23, 5-Leads, Body 2.9x1.6mm, Pitch 0.95mm, Lead Span 2.8mm, IPC Low Density)
pins: 1 RST (out), 2 GND (power), 3 ~{MR} (in), 4 RST IN (in), 5 VCC (power)

## MAX6312UK50D3-T
designator U?
5-Pin, Multiple-Input, Programmable Reset IC
footprint SOT23-5_N (SOT23, 5-Leads, Body 2.9x1.6mm, Pitch 0.95mm, Lead Span 2.8mm, IPC Medium Density)
footprint SOT23-5_L (SOT23, 5-Leads, Body 2.9x1.6mm, Pitch 0.95mm, Lead Span 2.8mm, IPC High Density)
footprint SOT23-5_M (SOT23, 5-Leads, Body 2.9x1.6mm, Pitch 0.95mm, Lead Span 2.8mm, IPC Low Density)
pins: 1 RST (out), 2 GND (power), 3 ~{MR} (in), 4 RST IN (in), 5 VCC (power)

## MAX6312UK50D4-T
designator U?
5-Pin, Multiple-Input, Programmable Reset IC
footprint SOT23-5_N (SOT23, 5-Leads, Body 2.9x1.6mm, Pitch 0.95mm, Lead Span 2.8mm, IPC Medium Density)
footprint SOT23-5_L (SOT23, 5-Leads, Body 2.9x1.6mm, Pitch 0.95mm, Lead Span 2.8mm, IPC High Density)
footprint SOT23-5_M (SOT23, 5-Leads, Body 2.9x1.6mm, Pitch 0.95mm, Lead Span 2.8mm, IPC Low Density)
pins: 1 RST (out), 2 GND (power), 3 ~{MR} (in), 4 RST IN (in), 5 VCC (power)

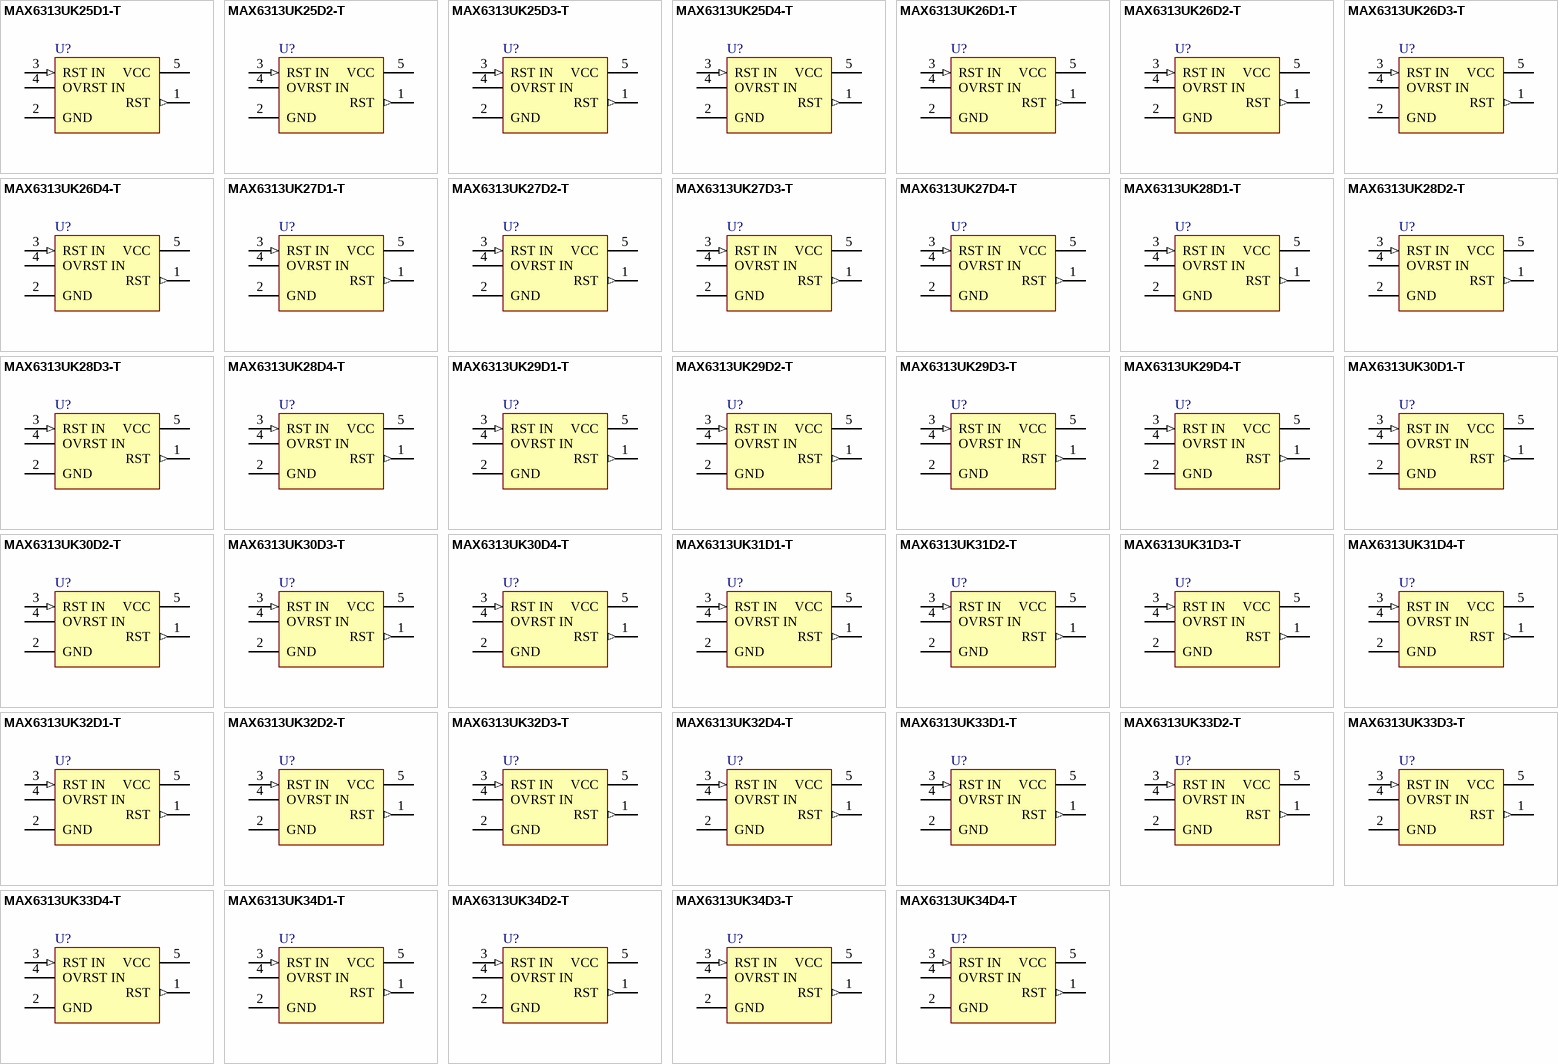
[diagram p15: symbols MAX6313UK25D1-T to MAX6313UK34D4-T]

## MAX6313UK25D1-T
designator U?
5-Pin, Multiple-Input, Programmable Reset IC
footprint SOT23-5_N (SOT23, 5-Leads, Body 2.9x1.6mm, Pitch 0.95mm, Lead Span 2.8mm, IPC Medium Density)
footprint SOT23-5_L (SOT23, 5-Leads, Body 2.9x1.6mm, Pitch 0.95mm, Lead Span 2.8mm, IPC High Density)
footprint SOT23-5_M (SOT23, 5-Leads, Body 2.9x1.6mm, Pitch 0.95mm, Lead Span 2.8mm, IPC Low Density)
pins: 1 RST (out), 2 GND (power), 3 RST IN (in), 4 OVRST IN, 5 VCC (power)

## MAX6313UK25D2-T
designator U?
5-Pin, Multiple-Input, Programmable Reset IC
footprint SOT23-5_N (SOT23, 5-Leads, Body 2.9x1.6mm, Pitch 0.95mm, Lead Span 2.8mm, IPC Medium Density)
footprint SOT23-5_L (SOT23, 5-Leads, Body 2.9x1.6mm, Pitch 0.95mm, Lead Span 2.8mm, IPC High Density)
footprint SOT23-5_M (SOT23, 5-Leads, Body 2.9x1.6mm, Pitch 0.95mm, Lead Span 2.8mm, IPC Low Density)
pins: 1 RST (out), 2 GND (power), 3 RST IN (in), 4 OVRST IN, 5 VCC (power)

## MAX6313UK25D3-T
designator U?
5-Pin, Multiple-Input, Programmable Reset IC
footprint SOT23-5_N (SOT23, 5-Leads, Body 2.9x1.6mm, Pitch 0.95mm, Lead Span 2.8mm, IPC Medium Density)
footprint SOT23-5_L (SOT23, 5-Leads, Body 2.9x1.6mm, Pitch 0.95mm, Lead Span 2.8mm, IPC High Density)
footprint SOT23-5_M (SOT23, 5-Leads, Body 2.9x1.6mm, Pitch 0.95mm, Lead Span 2.8mm, IPC Low Density)
pins: 1 RST (out), 2 GND (power), 3 RST IN (in), 4 OVRST IN, 5 VCC (power)

## MAX6313UK25D4-T
designator U?
5-Pin, Multiple-Input, Programmable Reset IC
footprint SOT23-5_N (SOT23, 5-Leads, Body 2.9x1.6mm, Pitch 0.95mm, Lead Span 2.8mm, IPC Medium Density)
footprint SOT23-5_L (SOT23, 5-Leads, Body 2.9x1.6mm, Pitch 0.95mm, Lead Span 2.8mm, IPC High Density)
footprint SOT23-5_M (SOT23, 5-Leads, Body 2.9x1.6mm, Pitch 0.95mm, Lead Span 2.8mm, IPC Low Density)
pins: 1 RST (out), 2 GND (power), 3 RST IN (in), 4 OVRST IN, 5 VCC (power)

## MAX6313UK26D1-T
designator U?
5-Pin, Multiple-Input, Programmable Reset IC
footprint SOT23-5_N (SOT23, 5-Leads, Body 2.9x1.6mm, Pitch 0.95mm, Lead Span 2.8mm, IPC Medium Density)
footprint SOT23-5_L (SOT23, 5-Leads, Body 2.9x1.6mm, Pitch 0.95mm, Lead Span 2.8mm, IPC High Density)
footprint SOT23-5_M (SOT23, 5-Leads, Body 2.9x1.6mm, Pitch 0.95mm, Lead Span 2.8mm, IPC Low Density)
pins: 1 RST (out), 2 GND (power), 3 RST IN (in), 4 OVRST IN, 5 VCC (power)

## MAX6313UK26D2-T
designator U?
5-Pin, Multiple-Input, Programmable Reset IC
footprint SOT23-5_N (SOT23, 5-Leads, Body 2.9x1.6mm, Pitch 0.95mm, Lead Span 2.8mm, IPC Medium Density)
footprint SOT23-5_L (SOT23, 5-Leads, Body 2.9x1.6mm, Pitch 0.95mm, Lead Span 2.8mm, IPC High Density)
footprint SOT23-5_M (SOT23, 5-Leads, Body 2.9x1.6mm, Pitch 0.95mm, Lead Span 2.8mm, IPC Low Density)
pins: 1 RST (out), 2 GND (power), 3 RST IN (in), 4 OVRST IN, 5 VCC (power)

## MAX6313UK26D3-T
designator U?
5-Pin, Multiple-Input, Programmable Reset IC
footprint SOT23-5_N (SOT23, 5-Leads, Body 2.9x1.6mm, Pitch 0.95mm, Lead Span 2.8mm, IPC Medium Density)
footprint SOT23-5_L (SOT23, 5-Leads, Body 2.9x1.6mm, Pitch 0.95mm, Lead Span 2.8mm, IPC High Density)
footprint SOT23-5_M (SOT23, 5-Leads, Body 2.9x1.6mm, Pitch 0.95mm, Lead Span 2.8mm, IPC Low Density)
pins: 1 RST (out), 2 GND (power), 3 RST IN (in), 4 OVRST IN, 5 VCC (power)

## MAX6313UK26D4-T
designator U?
5-Pin, Multiple-Input, Programmable Reset IC
footprint SOT23-5_N (SOT23, 5-Leads, Body 2.9x1.6mm, Pitch 0.95mm, Lead Span 2.8mm, IPC Medium Density)
footprint SOT23-5_L (SOT23, 5-Leads, Body 2.9x1.6mm, Pitch 0.95mm, Lead Span 2.8mm, IPC High Density)
footprint SOT23-5_M (SOT23, 5-Leads, Body 2.9x1.6mm, Pitch 0.95mm, Lead Span 2.8mm, IPC Low Density)
pins: 1 RST (out), 2 GND (power), 3 RST IN (in), 4 OVRST IN, 5 VCC (power)

## MAX6313UK27D1-T
designator U?
5-Pin, Multiple-Input, Programmable Reset IC
footprint SOT23-5_N (SOT23, 5-Leads, Body 2.9x1.6mm, Pitch 0.95mm, Lead Span 2.8mm, IPC Medium Density)
footprint SOT23-5_L (SOT23, 5-Leads, Body 2.9x1.6mm, Pitch 0.95mm, Lead Span 2.8mm, IPC High Density)
footprint SOT23-5_M (SOT23, 5-Leads, Body 2.9x1.6mm, Pitch 0.95mm, Lead Span 2.8mm, IPC Low Density)
pins: 1 RST (out), 2 GND (power), 3 RST IN (in), 4 OVRST IN, 5 VCC (power)

## MAX6313UK27D2-T
designator U?
5-Pin, Multiple-Input, Programmable Reset IC
footprint SOT23-5_N (SOT23, 5-Leads, Body 2.9x1.6mm, Pitch 0.95mm, Lead Span 2.8mm, IPC Medium Density)
footprint SOT23-5_L (SOT23, 5-Leads, Body 2.9x1.6mm, Pitch 0.95mm, Lead Span 2.8mm, IPC High Density)
footprint SOT23-5_M (SOT23, 5-Leads, Body 2.9x1.6mm, Pitch 0.95mm, Lead Span 2.8mm, IPC Low Density)
pins: 1 RST (out), 2 GND (power), 3 RST IN (in), 4 OVRST IN, 5 VCC (power)

## MAX6313UK27D3-T
designator U?
5-Pin, Multiple-Input, Programmable Reset IC
footprint SOT23-5_N (SOT23, 5-Leads, Body 2.9x1.6mm, Pitch 0.95mm, Lead Span 2.8mm, IPC Medium Density)
footprint SOT23-5_L (SOT23, 5-Leads, Body 2.9x1.6mm, Pitch 0.95mm, Lead Span 2.8mm, IPC High Density)
footprint SOT23-5_M (SOT23, 5-Leads, Body 2.9x1.6mm, Pitch 0.95mm, Lead Span 2.8mm, IPC Low Density)
pins: 1 RST (out), 2 GND (power), 3 RST IN (in), 4 OVRST IN, 5 VCC (power)

## MAX6313UK27D4-T
designator U?
5-Pin, Multiple-Input, Programmable Reset IC
footprint SOT23-5_N (SOT23, 5-Leads, Body 2.9x1.6mm, Pitch 0.95mm, Lead Span 2.8mm, IPC Medium Density)
footprint SOT23-5_L (SOT23, 5-Leads, Body 2.9x1.6mm, Pitch 0.95mm, Lead Span 2.8mm, IPC High Density)
footprint SOT23-5_M (SOT23, 5-Leads, Body 2.9x1.6mm, Pitch 0.95mm, Lead Span 2.8mm, IPC Low Density)
pins: 1 RST (out), 2 GND (power), 3 RST IN (in), 4 OVRST IN, 5 VCC (power)

## MAX6313UK28D1-T
designator U?
5-Pin, Multiple-Input, Programmable Reset IC
footprint SOT23-5_N (SOT23, 5-Leads, Body 2.9x1.6mm, Pitch 0.95mm, Lead Span 2.8mm, IPC Medium Density)
footprint SOT23-5_L (SOT23, 5-Leads, Body 2.9x1.6mm, Pitch 0.95mm, Lead Span 2.8mm, IPC High Density)
footprint SOT23-5_M (SOT23, 5-Leads, Body 2.9x1.6mm, Pitch 0.95mm, Lead Span 2.8mm, IPC Low Density)
pins: 1 RST (out), 2 GND (power), 3 RST IN (in), 4 OVRST IN, 5 VCC (power)

## MAX6313UK28D2-T
designator U?
5-Pin, Multiple-Input, Programmable Reset IC
footprint SOT23-5_N (SOT23, 5-Leads, Body 2.9x1.6mm, Pitch 0.95mm, Lead Span 2.8mm, IPC Medium Density)
footprint SOT23-5_L (SOT23, 5-Leads, Body 2.9x1.6mm, Pitch 0.95mm, Lead Span 2.8mm, IPC High Density)
footprint SOT23-5_M (SOT23, 5-Leads, Body 2.9x1.6mm, Pitch 0.95mm, Lead Span 2.8mm, IPC Low Density)
pins: 1 RST (out), 2 GND (power), 3 RST IN (in), 4 OVRST IN, 5 VCC (power)

## MAX6313UK28D3-T
designator U?
5-Pin, Multiple-Input, Programmable Reset IC
footprint SOT23-5_N (SOT23, 5-Leads, Body 2.9x1.6mm, Pitch 0.95mm, Lead Span 2.8mm, IPC Medium Density)
footprint SOT23-5_L (SOT23, 5-Leads, Body 2.9x1.6mm, Pitch 0.95mm, Lead Span 2.8mm, IPC High Density)
footprint SOT23-5_M (SOT23, 5-Leads, Body 2.9x1.6mm, Pitch 0.95mm, Lead Span 2.8mm, IPC Low Density)
pins: 1 RST (out), 2 GND (power), 3 RST IN (in), 4 OVRST IN, 5 VCC (power)

## MAX6313UK28D4-T
designator U?
5-Pin, Multiple-Input, Programmable Reset IC
footprint SOT23-5_N (SOT23, 5-Leads, Body 2.9x1.6mm, Pitch 0.95mm, Lead Span 2.8mm, IPC Medium Density)
footprint SOT23-5_L (SOT23, 5-Leads, Body 2.9x1.6mm, Pitch 0.95mm, Lead Span 2.8mm, IPC High Density)
footprint SOT23-5_M (SOT23, 5-Leads, Body 2.9x1.6mm, Pitch 0.95mm, Lead Span 2.8mm, IPC Low Density)
pins: 1 RST (out), 2 GND (power), 3 RST IN (in), 4 OVRST IN, 5 VCC (power)

## MAX6313UK29D1-T
designator U?
5-Pin, Multiple-Input, Programmable Reset IC
footprint SOT23-5_N (SOT23, 5-Leads, Body 2.9x1.6mm, Pitch 0.95mm, Lead Span 2.8mm, IPC Medium Density)
footprint SOT23-5_L (SOT23, 5-Leads, Body 2.9x1.6mm, Pitch 0.95mm, Lead Span 2.8mm, IPC High Density)
footprint SOT23-5_M (SOT23, 5-Leads, Body 2.9x1.6mm, Pitch 0.95mm, Lead Span 2.8mm, IPC Low Density)
pins: 1 RST (out), 2 GND (power), 3 RST IN (in), 4 OVRST IN, 5 VCC (power)

## MAX6313UK29D2-T
designator U?
5-Pin, Multiple-Input, Programmable Reset IC
footprint SOT23-5_N (SOT23, 5-Leads, Body 2.9x1.6mm, Pitch 0.95mm, Lead Span 2.8mm, IPC Medium Density)
footprint SOT23-5_L (SOT23, 5-Leads, Body 2.9x1.6mm, Pitch 0.95mm, Lead Span 2.8mm, IPC High Density)
footprint SOT23-5_M (SOT23, 5-Leads, Body 2.9x1.6mm, Pitch 0.95mm, Lead Span 2.8mm, IPC Low Density)
pins: 1 RST (out), 2 GND (power), 3 RST IN (in), 4 OVRST IN, 5 VCC (power)

## MAX6313UK29D3-T
designator U?
5-Pin, Multiple-Input, Programmable Reset IC
footprint SOT23-5_N (SOT23, 5-Leads, Body 2.9x1.6mm, Pitch 0.95mm, Lead Span 2.8mm, IPC Medium Density)
footprint SOT23-5_L (SOT23, 5-Leads, Body 2.9x1.6mm, Pitch 0.95mm, Lead Span 2.8mm, IPC High Density)
footprint SOT23-5_M (SOT23, 5-Leads, Body 2.9x1.6mm, Pitch 0.95mm, Lead Span 2.8mm, IPC Low Density)
pins: 1 RST (out), 2 GND (power), 3 RST IN (in), 4 OVRST IN, 5 VCC (power)

## MAX6313UK29D4-T
designator U?
5-Pin, Multiple-Input, Programmable Reset IC
footprint SOT23-5_N (SOT23, 5-Leads, Body 2.9x1.6mm, Pitch 0.95mm, Lead Span 2.8mm, IPC Medium Density)
footprint SOT23-5_L (SOT23, 5-Leads, Body 2.9x1.6mm, Pitch 0.95mm, Lead Span 2.8mm, IPC High Density)
footprint SOT23-5_M (SOT23, 5-Leads, Body 2.9x1.6mm, Pitch 0.95mm, Lead Span 2.8mm, IPC Low Density)
pins: 1 RST (out), 2 GND (power), 3 RST IN (in), 4 OVRST IN, 5 VCC (power)

## MAX6313UK30D1-T
designator U?
5-Pin, Multiple-Input, Programmable Reset IC
footprint SOT23-5_N (SOT23, 5-Leads, Body 2.9x1.6mm, Pitch 0.95mm, Lead Span 2.8mm, IPC Medium Density)
footprint SOT23-5_L (SOT23, 5-Leads, Body 2.9x1.6mm, Pitch 0.95mm, Lead Span 2.8mm, IPC High Density)
footprint SOT23-5_M (SOT23, 5-Leads, Body 2.9x1.6mm, Pitch 0.95mm, Lead Span 2.8mm, IPC Low Density)
pins: 1 RST (out), 2 GND (power), 3 RST IN (in), 4 OVRST IN, 5 VCC (power)

## MAX6313UK30D2-T
designator U?
5-Pin, Multiple-Input, Programmable Reset IC
footprint SOT23-5_N (SOT23, 5-Leads, Body 2.9x1.6mm, Pitch 0.95mm, Lead Span 2.8mm, IPC Medium Density)
footprint SOT23-5_L (SOT23, 5-Leads, Body 2.9x1.6mm, Pitch 0.95mm, Lead Span 2.8mm, IPC High Density)
footprint SOT23-5_M (SOT23, 5-Leads, Body 2.9x1.6mm, Pitch 0.95mm, Lead Span 2.8mm, IPC Low Density)
pins: 1 RST (out), 2 GND (power), 3 RST IN (in), 4 OVRST IN, 5 VCC (power)

## MAX6313UK30D3-T
designator U?
5-Pin, Multiple-Input, Programmable Reset IC
footprint SOT23-5_N (SOT23, 5-Leads, Body 2.9x1.6mm, Pitch 0.95mm, Lead Span 2.8mm, IPC Medium Density)
footprint SOT23-5_L (SOT23, 5-Leads, Body 2.9x1.6mm, Pitch 0.95mm, Lead Span 2.8mm, IPC High Density)
footprint SOT23-5_M (SOT23, 5-Leads, Body 2.9x1.6mm, Pitch 0.95mm, Lead Span 2.8mm, IPC Low Density)
pins: 1 RST (out), 2 GND (power), 3 RST IN (in), 4 OVRST IN, 5 VCC (power)

## MAX6313UK30D4-T
designator U?
5-Pin, Multiple-Input, Programmable Reset IC
footprint SOT23-5_N (SOT23, 5-Leads, Body 2.9x1.6mm, Pitch 0.95mm, Lead Span 2.8mm, IPC Medium Density)
footprint SOT23-5_L (SOT23, 5-Leads, Body 2.9x1.6mm, Pitch 0.95mm, Lead Span 2.8mm, IPC High Density)
footprint SOT23-5_M (SOT23, 5-Leads, Body 2.9x1.6mm, Pitch 0.95mm, Lead Span 2.8mm, IPC Low Density)
pins: 1 RST (out), 2 GND (power), 3 RST IN (in), 4 OVRST IN, 5 VCC (power)

## MAX6313UK31D1-T
designator U?
5-Pin, Multiple-Input, Programmable Reset IC
footprint SOT23-5_N (SOT23, 5-Leads, Body 2.9x1.6mm, Pitch 0.95mm, Lead Span 2.8mm, IPC Medium Density)
footprint SOT23-5_L (SOT23, 5-Leads, Body 2.9x1.6mm, Pitch 0.95mm, Lead Span 2.8mm, IPC High Density)
footprint SOT23-5_M (SOT23, 5-Leads, Body 2.9x1.6mm, Pitch 0.95mm, Lead Span 2.8mm, IPC Low Density)
pins: 1 RST (out), 2 GND (power), 3 RST IN (in), 4 OVRST IN, 5 VCC (power)

## MAX6313UK31D2-T
designator U?
5-Pin, Multiple-Input, Programmable Reset IC
footprint SOT23-5_N (SOT23, 5-Leads, Body 2.9x1.6mm, Pitch 0.95mm, Lead Span 2.8mm, IPC Medium Density)
footprint SOT23-5_L (SOT23, 5-Leads, Body 2.9x1.6mm, Pitch 0.95mm, Lead Span 2.8mm, IPC High Density)
footprint SOT23-5_M (SOT23, 5-Leads, Body 2.9x1.6mm, Pitch 0.95mm, Lead Span 2.8mm, IPC Low Density)
pins: 1 RST (out), 2 GND (power), 3 RST IN (in), 4 OVRST IN, 5 VCC (power)

## MAX6313UK31D3-T
designator U?
5-Pin, Multiple-Input, Programmable Reset IC
footprint SOT23-5_N (SOT23, 5-Leads, Body 2.9x1.6mm, Pitch 0.95mm, Lead Span 2.8mm, IPC Medium Density)
footprint SOT23-5_L (SOT23, 5-Leads, Body 2.9x1.6mm, Pitch 0.95mm, Lead Span 2.8mm, IPC High Density)
footprint SOT23-5_M (SOT23, 5-Leads, Body 2.9x1.6mm, Pitch 0.95mm, Lead Span 2.8mm, IPC Low Density)
pins: 1 RST (out), 2 GND (power), 3 RST IN (in), 4 OVRST IN, 5 VCC (power)

## MAX6313UK31D4-T
designator U?
5-Pin, Multiple-Input, Programmable Reset IC
footprint SOT23-5_N (SOT23, 5-Leads, Body 2.9x1.6mm, Pitch 0.95mm, Lead Span 2.8mm, IPC Medium Density)
footprint SOT23-5_L (SOT23, 5-Leads, Body 2.9x1.6mm, Pitch 0.95mm, Lead Span 2.8mm, IPC High Density)
footprint SOT23-5_M (SOT23, 5-Leads, Body 2.9x1.6mm, Pitch 0.95mm, Lead Span 2.8mm, IPC Low Density)
pins: 1 RST (out), 2 GND (power), 3 RST IN (in), 4 OVRST IN, 5 VCC (power)

## MAX6313UK32D1-T
designator U?
5-Pin, Multiple-Input, Programmable Reset IC
footprint SOT23-5_N (SOT23, 5-Leads, Body 2.9x1.6mm, Pitch 0.95mm, Lead Span 2.8mm, IPC Medium Density)
footprint SOT23-5_L (SOT23, 5-Leads, Body 2.9x1.6mm, Pitch 0.95mm, Lead Span 2.8mm, IPC High Density)
footprint SOT23-5_M (SOT23, 5-Leads, Body 2.9x1.6mm, Pitch 0.95mm, Lead Span 2.8mm, IPC Low Density)
pins: 1 RST (out), 2 GND (power), 3 RST IN (in), 4 OVRST IN, 5 VCC (power)

## MAX6313UK32D2-T
designator U?
5-Pin, Multiple-Input, Programmable Reset IC
footprint SOT23-5_N (SOT23, 5-Leads, Body 2.9x1.6mm, Pitch 0.95mm, Lead Span 2.8mm, IPC Medium Density)
footprint SOT23-5_L (SOT23, 5-Leads, Body 2.9x1.6mm, Pitch 0.95mm, Lead Span 2.8mm, IPC High Density)
footprint SOT23-5_M (SOT23, 5-Leads, Body 2.9x1.6mm, Pitch 0.95mm, Lead Span 2.8mm, IPC Low Density)
pins: 1 RST (out), 2 GND (power), 3 RST IN (in), 4 OVRST IN, 5 VCC (power)

## MAX6313UK32D3-T
designator U?
5-Pin, Multiple-Input, Programmable Reset IC
footprint SOT23-5_N (SOT23, 5-Leads, Body 2.9x1.6mm, Pitch 0.95mm, Lead Span 2.8mm, IPC Medium Density)
footprint SOT23-5_L (SOT23, 5-Leads, Body 2.9x1.6mm, Pitch 0.95mm, Lead Span 2.8mm, IPC High Density)
footprint SOT23-5_M (SOT23, 5-Leads, Body 2.9x1.6mm, Pitch 0.95mm, Lead Span 2.8mm, IPC Low Density)
pins: 1 RST (out), 2 GND (power), 3 RST IN (in), 4 OVRST IN, 5 VCC (power)

## MAX6313UK32D4-T
designator U?
5-Pin, Multiple-Input, Programmable Reset IC
footprint SOT23-5_N (SOT23, 5-Leads, Body 2.9x1.6mm, Pitch 0.95mm, Lead Span 2.8mm, IPC Medium Density)
footprint SOT23-5_L (SOT23, 5-Leads, Body 2.9x1.6mm, Pitch 0.95mm, Lead Span 2.8mm, IPC High Density)
footprint SOT23-5_M (SOT23, 5-Leads, Body 2.9x1.6mm, Pitch 0.95mm, Lead Span 2.8mm, IPC Low Density)
pins: 1 RST (out), 2 GND (power), 3 RST IN (in), 4 OVRST IN, 5 VCC (power)

## MAX6313UK33D1-T
designator U?
5-Pin, Multiple-Input, Programmable Reset IC
footprint SOT23-5_N (SOT23, 5-Leads, Body 2.9x1.6mm, Pitch 0.95mm, Lead Span 2.8mm, IPC Medium Density)
footprint SOT23-5_L (SOT23, 5-Leads, Body 2.9x1.6mm, Pitch 0.95mm, Lead Span 2.8mm, IPC High Density)
footprint SOT23-5_M (SOT23, 5-Leads, Body 2.9x1.6mm, Pitch 0.95mm, Lead Span 2.8mm, IPC Low Density)
pins: 1 RST (out), 2 GND (power), 3 RST IN (in), 4 OVRST IN, 5 VCC (power)

## MAX6313UK33D2-T
designator U?
5-Pin, Multiple-Input, Programmable Reset IC
footprint SOT23-5_N (SOT23, 5-Leads, Body 2.9x1.6mm, Pitch 0.95mm, Lead Span 2.8mm, IPC Medium Density)
footprint SOT23-5_L (SOT23, 5-Leads, Body 2.9x1.6mm, Pitch 0.95mm, Lead Span 2.8mm, IPC High Density)
footprint SOT23-5_M (SOT23, 5-Leads, Body 2.9x1.6mm, Pitch 0.95mm, Lead Span 2.8mm, IPC Low Density)
pins: 1 RST (out), 2 GND (power), 3 RST IN (in), 4 OVRST IN, 5 VCC (power)

## MAX6313UK33D3-T
designator U?
5-Pin, Multiple-Input, Programmable Reset IC
footprint SOT23-5_N (SOT23, 5-Leads, Body 2.9x1.6mm, Pitch 0.95mm, Lead Span 2.8mm, IPC Medium Density)
footprint SOT23-5_L (SOT23, 5-Leads, Body 2.9x1.6mm, Pitch 0.95mm, Lead Span 2.8mm, IPC High Density)
footprint SOT23-5_M (SOT23, 5-Leads, Body 2.9x1.6mm, Pitch 0.95mm, Lead Span 2.8mm, IPC Low Density)
pins: 1 RST (out), 2 GND (power), 3 RST IN (in), 4 OVRST IN, 5 VCC (power)

## MAX6313UK33D4-T
designator U?
5-Pin, Multiple-Input, Programmable Reset IC
footprint SOT23-5_N (SOT23, 5-Leads, Body 2.9x1.6mm, Pitch 0.95mm, Lead Span 2.8mm, IPC Medium Density)
footprint SOT23-5_L (SOT23, 5-Leads, Body 2.9x1.6mm, Pitch 0.95mm, Lead Span 2.8mm, IPC High Density)
footprint SOT23-5_M (SOT23, 5-Leads, Body 2.9x1.6mm, Pitch 0.95mm, Lead Span 2.8mm, IPC Low Density)
pins: 1 RST (out), 2 GND (power), 3 RST IN (in), 4 OVRST IN, 5 VCC (power)

## MAX6313UK34D1-T
designator U?
5-Pin, Multiple-Input, Programmable Reset IC
footprint SOT23-5_N (SOT23, 5-Leads, Body 2.9x1.6mm, Pitch 0.95mm, Lead Span 2.8mm, IPC Medium Density)
footprint SOT23-5_L (SOT23, 5-Leads, Body 2.9x1.6mm, Pitch 0.95mm, Lead Span 2.8mm, IPC High Density)
footprint SOT23-5_M (SOT23, 5-Leads, Body 2.9x1.6mm, Pitch 0.95mm, Lead Span 2.8mm, IPC Low Density)
pins: 1 RST (out), 2 GND (power), 3 RST IN (in), 4 OVRST IN, 5 VCC (power)

## MAX6313UK34D2-T
designator U?
5-Pin, Multiple-Input, Programmable Reset IC
footprint SOT23-5_N (SOT23, 5-Leads, Body 2.9x1.6mm, Pitch 0.95mm, Lead Span 2.8mm, IPC Medium Density)
footprint SOT23-5_L (SOT23, 5-Leads, Body 2.9x1.6mm, Pitch 0.95mm, Lead Span 2.8mm, IPC High Density)
footprint SOT23-5_M (SOT23, 5-Leads, Body 2.9x1.6mm, Pitch 0.95mm, Lead Span 2.8mm, IPC Low Density)
pins: 1 RST (out), 2 GND (power), 3 RST IN (in), 4 OVRST IN, 5 VCC (power)

## MAX6313UK34D3-T
designator U?
5-Pin, Multiple-Input, Programmable Reset IC
footprint SOT23-5_N (SOT23, 5-Leads, Body 2.9x1.6mm, Pitch 0.95mm, Lead Span 2.8mm, IPC Medium Density)
footprint SOT23-5_L (SOT23, 5-Leads, Body 2.9x1.6mm, Pitch 0.95mm, Lead Span 2.8mm, IPC High Density)
footprint SOT23-5_M (SOT23, 5-Leads, Body 2.9x1.6mm, Pitch 0.95mm, Lead Span 2.8mm, IPC Low Density)
pins: 1 RST (out), 2 GND (power), 3 RST IN (in), 4 OVRST IN, 5 VCC (power)

## MAX6313UK34D4-T
designator U?
5-Pin, Multiple-Input, Programmable Reset IC
footprint SOT23-5_N (SOT23, 5-Leads, Body 2.9x1.6mm, Pitch 0.95mm, Lead Span 2.8mm, IPC Medium Density)
footprint SOT23-5_L (SOT23, 5-Leads, Body 2.9x1.6mm, Pitch 0.95mm, Lead Span 2.8mm, IPC High Density)
footprint SOT23-5_M (SOT23, 5-Leads, Body 2.9x1.6mm, Pitch 0.95mm, Lead Span 2.8mm, IPC Low Density)
pins: 1 RST (out), 2 GND (power), 3 RST IN (in), 4 OVRST IN, 5 VCC (power)

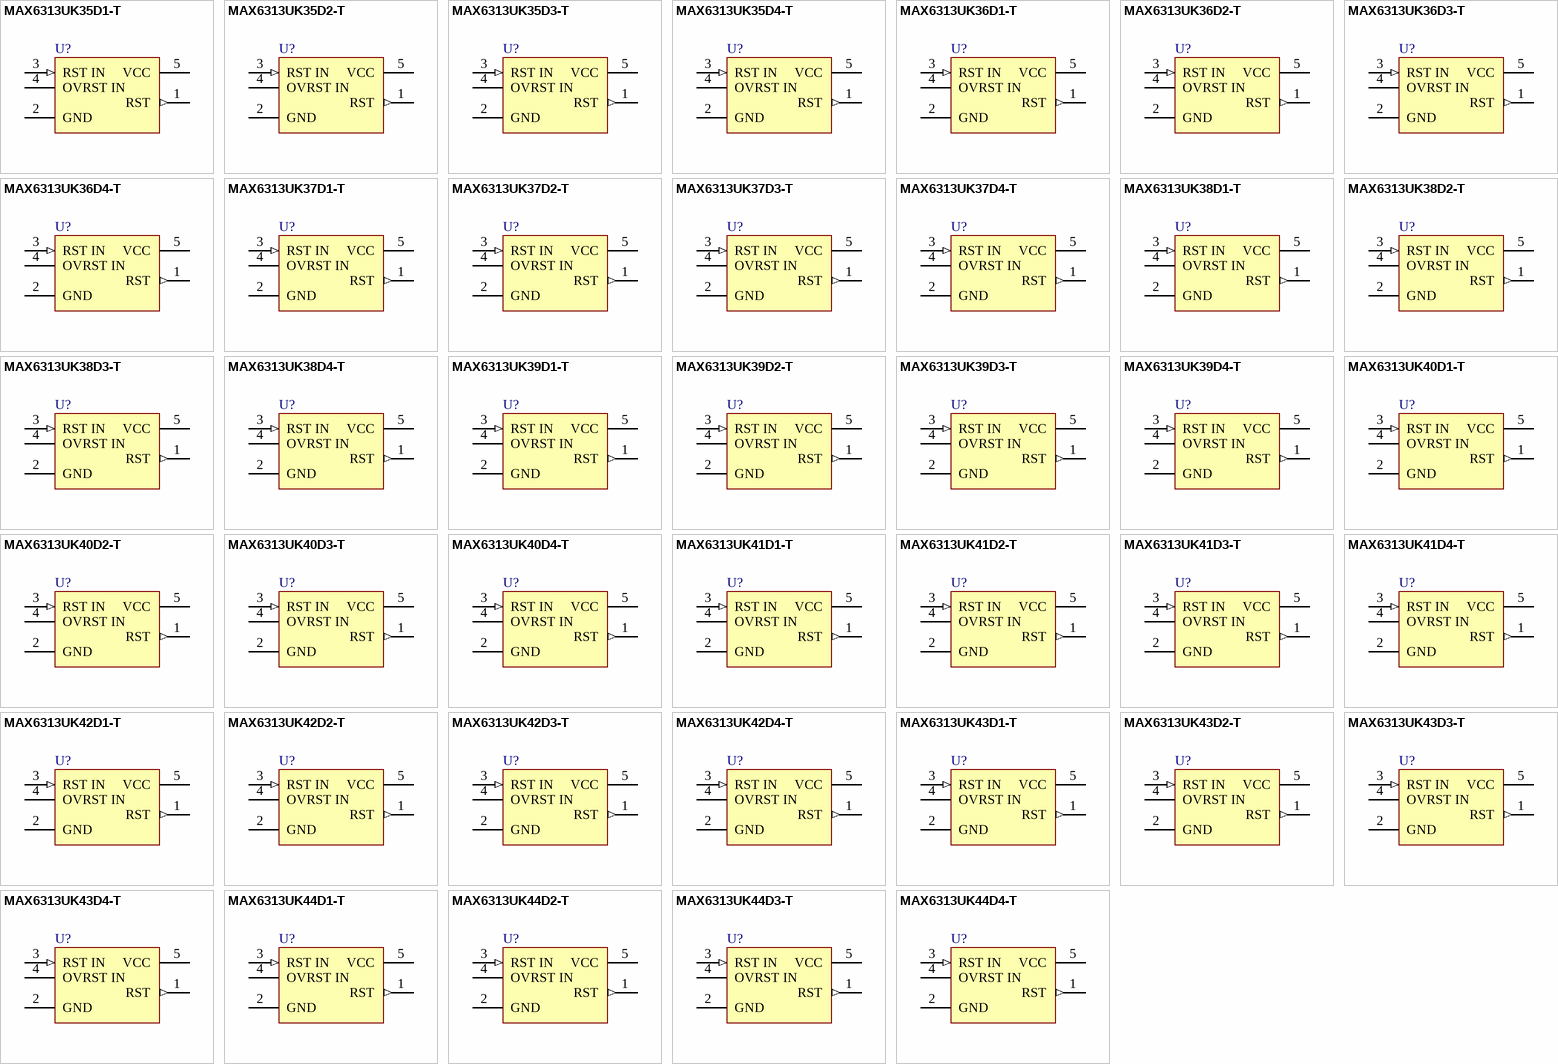
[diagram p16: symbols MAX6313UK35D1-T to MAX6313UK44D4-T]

## MAX6313UK35D1-T
designator U?
5-Pin, Multiple-Input, Programmable Reset IC
footprint SOT23-5_N (SOT23, 5-Leads, Body 2.9x1.6mm, Pitch 0.95mm, Lead Span 2.8mm, IPC Medium Density)
footprint SOT23-5_L (SOT23, 5-Leads, Body 2.9x1.6mm, Pitch 0.95mm, Lead Span 2.8mm, IPC High Density)
footprint SOT23-5_M (SOT23, 5-Leads, Body 2.9x1.6mm, Pitch 0.95mm, Lead Span 2.8mm, IPC Low Density)
pins: 1 RST (out), 2 GND (power), 3 RST IN (in), 4 OVRST IN, 5 VCC (power)

## MAX6313UK35D2-T
designator U?
5-Pin, Multiple-Input, Programmable Reset IC
footprint SOT23-5_N (SOT23, 5-Leads, Body 2.9x1.6mm, Pitch 0.95mm, Lead Span 2.8mm, IPC Medium Density)
footprint SOT23-5_L (SOT23, 5-Leads, Body 2.9x1.6mm, Pitch 0.95mm, Lead Span 2.8mm, IPC High Density)
footprint SOT23-5_M (SOT23, 5-Leads, Body 2.9x1.6mm, Pitch 0.95mm, Lead Span 2.8mm, IPC Low Density)
pins: 1 RST (out), 2 GND (power), 3 RST IN (in), 4 OVRST IN, 5 VCC (power)

## MAX6313UK35D3-T
designator U?
5-Pin, Multiple-Input, Programmable Reset IC
footprint SOT23-5_N (SOT23, 5-Leads, Body 2.9x1.6mm, Pitch 0.95mm, Lead Span 2.8mm, IPC Medium Density)
footprint SOT23-5_L (SOT23, 5-Leads, Body 2.9x1.6mm, Pitch 0.95mm, Lead Span 2.8mm, IPC High Density)
footprint SOT23-5_M (SOT23, 5-Leads, Body 2.9x1.6mm, Pitch 0.95mm, Lead Span 2.8mm, IPC Low Density)
pins: 1 RST (out), 2 GND (power), 3 RST IN (in), 4 OVRST IN, 5 VCC (power)

## MAX6313UK35D4-T
designator U?
5-Pin, Multiple-Input, Programmable Reset IC
footprint SOT23-5_N (SOT23, 5-Leads, Body 2.9x1.6mm, Pitch 0.95mm, Lead Span 2.8mm, IPC Medium Density)
footprint SOT23-5_L (SOT23, 5-Leads, Body 2.9x1.6mm, Pitch 0.95mm, Lead Span 2.8mm, IPC High Density)
footprint SOT23-5_M (SOT23, 5-Leads, Body 2.9x1.6mm, Pitch 0.95mm, Lead Span 2.8mm, IPC Low Density)
pins: 1 RST (out), 2 GND (power), 3 RST IN (in), 4 OVRST IN, 5 VCC (power)

## MAX6313UK36D1-T
designator U?
5-Pin, Multiple-Input, Programmable Reset IC
footprint SOT23-5_N (SOT23, 5-Leads, Body 2.9x1.6mm, Pitch 0.95mm, Lead Span 2.8mm, IPC Medium Density)
footprint SOT23-5_L (SOT23, 5-Leads, Body 2.9x1.6mm, Pitch 0.95mm, Lead Span 2.8mm, IPC High Density)
footprint SOT23-5_M (SOT23, 5-Leads, Body 2.9x1.6mm, Pitch 0.95mm, Lead Span 2.8mm, IPC Low Density)
pins: 1 RST (out), 2 GND (power), 3 RST IN (in), 4 OVRST IN, 5 VCC (power)

## MAX6313UK36D2-T
designator U?
5-Pin, Multiple-Input, Programmable Reset IC
footprint SOT23-5_N (SOT23, 5-Leads, Body 2.9x1.6mm, Pitch 0.95mm, Lead Span 2.8mm, IPC Medium Density)
footprint SOT23-5_L (SOT23, 5-Leads, Body 2.9x1.6mm, Pitch 0.95mm, Lead Span 2.8mm, IPC High Density)
footprint SOT23-5_M (SOT23, 5-Leads, Body 2.9x1.6mm, Pitch 0.95mm, Lead Span 2.8mm, IPC Low Density)
pins: 1 RST (out), 2 GND (power), 3 RST IN (in), 4 OVRST IN, 5 VCC (power)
